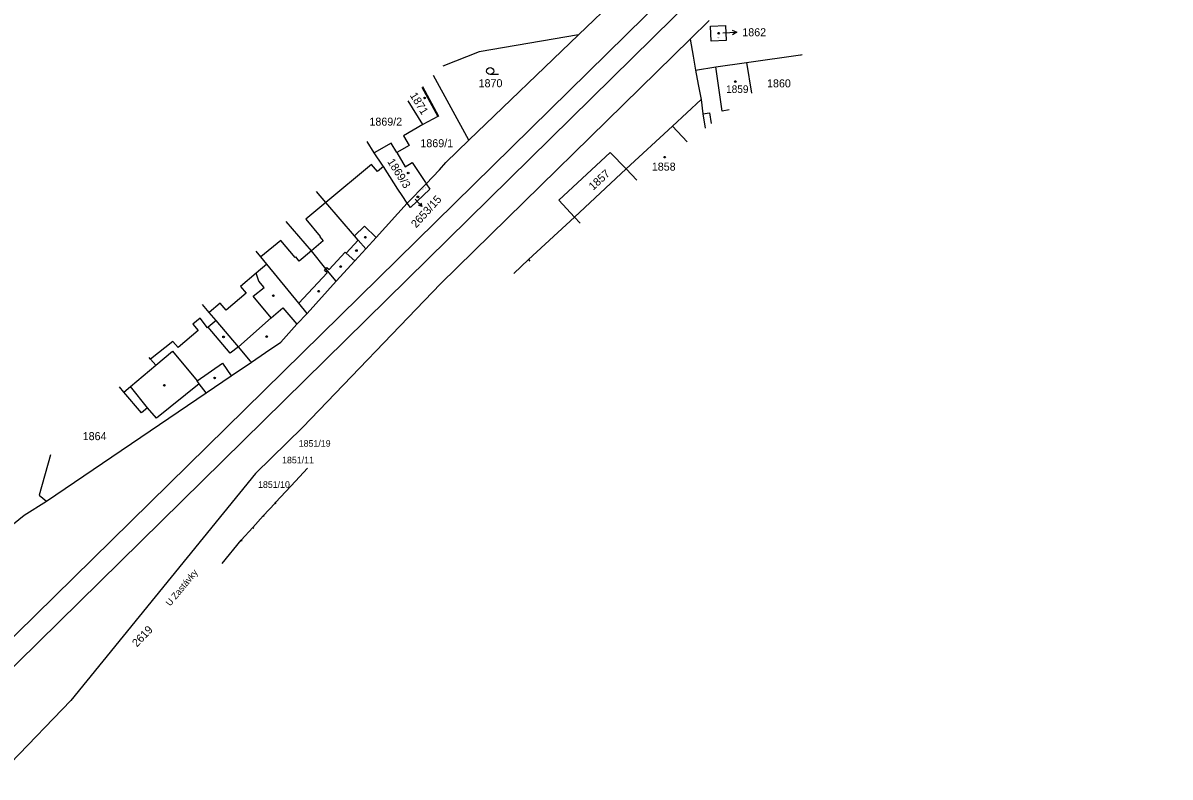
# Model space of a CAD drawing. Extents: x -825057 to -819383, y -1071633 to -1067888.
# Drawn here: x -819637.1 to -819393.5, y -1069088.6 to -1068928.5 of the extents above; entities that cross this region are included whole.
import ezdxf

# ---------------------------------------------------------------- set-up
doc = ezdxf.new("R2010")
doc.units = 0
for name, color, linetype in [('Vrstva 1', 7, 'Continuous'), ('Vrstva 10', 7, 'Continuous'), ('Vrstva 15', 7, 'Continuous'), ('Vrstva 16', 7, 'Continuous'), ('Vrstva 18', 7, 'Continuous'), ('Vrstva 19', 7, 'Continuous'), ('Vrstva 25', 7, 'Continuous'), ('Vrstva 4', 7, 'Continuous')]:
    doc.layers.add(name, color=color, linetype=linetype)

msp = doc.modelspace()

# ---------------------------------------------------------------- linework, layer by layer
at = {"layer": 'Vrstva 1'}
for p, q in [((-819519.1, -1068931.03), (-819503.43, -1068916.02)), ((-819491.32, -1068927.98), (-819495.4, -1068931.98)), ((-819542.35, -1068953.43), (-819519.1, -1068931.03)), ((-819519.1, -1068931.03), (-819540.17, -1068934.68)), ((-819491.07, -1068929.21), (-819487.91, -1068929.05)), ((-819490.92, -1068932.37), (-819491.07, -1068929.21)), ((-819487.91, -1068929.05), (-819487.75, -1068932.21)), ((-819495.4, -1068931.98), (-819548.4, -1068983.89)), ((-819495.4, -1068931.98), (-819494.75, -1068935.57)), ((-819487.75, -1068932.21), (-819490.92, -1068932.37)), ((-819540.17, -1068934.68), (-819547.89, -1068937.7)), ((-819494.75, -1068935.57), (-819494.22, -1068938.52)), ((-819483.41, -1068936.92), (-819471.97, -1068935.25)), ((-819471.97, -1068935.25), (-819471.6, -1068935.2)), ((-819471.97, -1068935.25), (-819471.94, -1068935.45)), ((-819494.22, -1068938.52), (-819489.95, -1068937.86)), ((-819494.22, -1068938.52), (-819493.67, -1068941.57)), ((-819489.95, -1068937.86), (-819483.41, -1068936.92)), ((-819483.41, -1068936.92), (-819482.39, -1068943.39)), ((-819542.35, -1068953.43), (-819549.86, -1068939.66)), ((-819552.25, -1068942.02), (-819548.82, -1068948.31)), ((-819493.67, -1068941.57), (-819493.08, -1068944.79)), ((-819552.14, -1068950.11), (-819555.27, -1068945.02)), ((-819493.08, -1068944.79), (-819499.16, -1068950.4)), ((-819493.08, -1068944.79), (-819492.69, -1068947.79)), ((-819548.82, -1068948.31), (-819548.99, -1068948.4)), ((-819492.69, -1068947.79), (-819492.18, -1068950.82)), ((-819552.14, -1068950.11), (-819556.24, -1068952.51)), ((-819548.99, -1068948.4), (-819552.14, -1068950.11)), ((-819499.16, -1068950.4), (-819508.94, -1068959.47)), ((-819556.24, -1068952.51), (-819555.06, -1068954.54)), ((-819562.45, -1068956.06), (-819564, -1068953.67)), ((-819558.89, -1068954.02), (-819562.45, -1068956.06)), ((-819557.68, -1068956.03), (-819558.89, -1068954.02)), ((-819555.06, -1068954.54), (-819557.68, -1068956.03)), ((-819547.27, -1068958.17), (-819542.35, -1068953.43)), ((-819560.72, -1068958.72), (-819562.45, -1068956.06)), ((-819557.68, -1068956.03), (-819555.87, -1068959.03)), ((-819512.39, -1068955.99), (-819523.26, -1068966.11)), ((-819508.94, -1068959.47), (-819512.39, -1068955.99)), ((-819560.53, -1068959.01), (-819560.72, -1068958.72)), ((-819558.31, -1068962.43), (-819560.53, -1068959.01)), ((-819555.87, -1068959.03), (-819554.4, -1068958.16)), ((-819554.4, -1068958.16), (-819551.61, -1068962.38)), ((-819551.44, -1068962.65), (-819548.59, -1068959.7)), ((-819548.59, -1068959.7), (-819547.27, -1068958.17)), ((-819508.94, -1068959.47), (-819519.95, -1068969.72)), ((-819508.94, -1068959.47), (-819506.72, -1068961.87)), ((-819557.43, -1068963.78), (-819558.31, -1068962.43)), ((-819555.46, -1068966.81), (-819551.44, -1068962.65)), ((-819551.61, -1068962.38), (-819551.44, -1068962.65)), ((-819551.44, -1068962.65), (-819550.66, -1068963.82)), ((-819572.74, -1068966.66), (-819574.73, -1068964.3)), ((-819556.56, -1068965.13), (-819557.43, -1068963.78)), ((-819555.46, -1068966.81), (-819556.56, -1068965.13)), ((-819550.66, -1068963.82), (-819554.74, -1068967.73)), ((-819566.69, -1068973.69), (-819572.74, -1068966.66)), ((-819562.05, -1068974.06), (-819555.46, -1068966.81)), ((-819554.74, -1068967.73), (-819555.46, -1068966.81)), ((-819523.26, -1068966.11), (-819519.95, -1068969.72)), ((-819519.95, -1068969.72), (-819529.74, -1068978.75)), ((-819519.95, -1068969.72), (-819518.74, -1068971)), ((-819575.82, -1068976.91), (-819581.14, -1068970.66)), ((-819565.88, -1068974.64), (-819566.69, -1068973.69)), ((-819564.27, -1068976.5), (-819565.88, -1068974.64)), ((-819564.27, -1068976.5), (-819562.05, -1068974.06)), ((-819586.52, -1068978.19), (-819587.54, -1068977)), ((-819572.73, -1068980.69), (-819575.82, -1068976.91)), ((-819566.58, -1068979.02), (-819564.27, -1068976.5)), ((-819585.24, -1068979.75), (-819586.52, -1068978.19)), ((-819578.49, -1068988.04), (-819585.24, -1068979.75)), ((-819570.53, -1068983.33), (-819566.58, -1068979.02)), ((-819529.74, -1068978.75), (-819532.85, -1068981.71)), ((-819529.74, -1068978.75), (-819529.42, -1068979.1)), ((-819570.53, -1068983.33), (-819572.73, -1068980.69)), ((-819548.4, -1068983.89), (-819577.66, -1069014.36)), ((-819576.73, -1068990.2), (-819570.53, -1068983.33)), ((-819597.52, -1068989.97), (-819598.94, -1068988.29)), ((-819576.73, -1068990.2), (-819578.49, -1068988.04)), ((-819596.03, -1068991.72), (-819597.52, -1068989.97)), ((-819591.26, -1068997.31), (-819596.03, -1068991.72)), ((-819578.88, -1068992.48), (-819576.73, -1068990.2)), ((-819582.32, -1068996.26), (-819578.88, -1068992.48)), ((-819585.57, -1068998.49), (-819582.32, -1068996.26)), ((-819588.71, -1069000.3), (-819591.26, -1068997.31)), ((-819588.52, -1069000.53), (-819585.57, -1068998.49)), ((-819592.84, -1069003.45), (-819588.52, -1069000.53)), ((-819588.52, -1069000.53), (-819588.71, -1069000.3)), ((-819598.18, -1069007.07), (-819592.84, -1069003.45)), ((-819615.6, -1069006.9), (-819616.56, -1069005.75)), ((-819599.61, -1069005.14), (-819608.7, -1069012.44)), ((-819598.18, -1069007.07), (-819599.61, -1069005.14)), ((-819632.07, -1069030.01), (-819598.18, -1069007.07)), ((-819611.9, -1069011.32), (-819615.6, -1069006.9)), ((-819610.61, -1069010.22), (-819611.9, -1069011.32)), ((-819608.7, -1069012.44), (-819610.61, -1069010.22)), ((-819577.66, -1069014.36), (-819587.71, -1069024.18)), ((-819631.17, -1069020.23), (-819633.59, -1069028.78)), ((-819579.17, -1069025.81), (-819576.62, -1069023.05)), ((-819587.71, -1069024.18), (-819626.91, -1069072.36)), ((-819583.33, -1069030.24), (-819579.17, -1069025.81)), ((-819636.82, -1069032.99), (-819632.07, -1069030.01)), ((-819633.59, -1069028.78), (-819632.07, -1069030.01)), ((-819586.02, -1069033.17), (-819583.53, -1069030.45)), ((-819583.53, -1069030.45), (-819583.33, -1069030.24)), ((-819583.19, -1069030.36), (-819583.33, -1069030.24)), ((-819659.02, -1069051.19), (-819636.82, -1069032.99)), ((-819588.24, -1069035.6), (-819586.02, -1069033.17)), ((-819585.84, -1069033.31), (-819586.02, -1069033.17)), ((-819590.73, -1069038.32), (-819588.24, -1069035.6)), ((-819588.24, -1069035.6), (-819588.04, -1069035.76)), ((-819594.78, -1069043.27), (-819590.73, -1069038.32)), ((-819590.73, -1069038.32), (-819590.5, -1069038.51)), ((-819626.91, -1069072.36), (-819639.73, -1069085.69))]:
    msp.add_line(p, q, dxfattribs=at)
at = {"layer": 'Vrstva 10'}
for p, q in [((-819896.02, -1069311.23), (-819396.47, -1068820.5)), ((-819393.49, -1068823.65), (-819892.75, -1069314.72))]:
    msp.add_line(p, q, dxfattribs=at)
at = {"layer": 'Vrstva 16'}
for p, q in [((-819488.45, -1068930.64), (-819485.454, -1068930.488)), ((-819553.78, -1068965.94), (-819552.327, -1068967.456))]:
    msp.add_line(p, q, dxfattribs=at)
for points in [[(-819486.478, -1068930.039), (-819485.454, -1068930.488), (-819486.427, -1068931.038)], [(-819552.559, -1068966.709), (-819552.327, -1068967.456), (-819553.064, -1068967.193)]]:
    msp.add_lwpolyline(points, dxfattribs=at)
at = {"layer": 'Vrstva 25'}
msp.add_line((-819536.1, -1068939.48), (-819537.85, -1068939.48), dxfattribs=at)
for centre, radius in [((-819489.33, -1068930.7), 0.175), ((-819537.85, -1068938.73), 0.75), ((-819485.8, -1068940.96), 0.175), ((-819551.77, -1068944.44), 0.175), ((-819500.79, -1068957.01), 0.175), ((-819555.26, -1068960.36), 0.175), ((-819553.2, -1068965.44), 0.175), ((-819564.34, -1068974), 0.175), ((-819566.24, -1068976.83), 0.175), ((-819569.58, -1068980.24), 0.175), ((-819583.88, -1068986.42), 0.175), ((-819574.25, -1068985.47), 0.175), ((-819594.46, -1068995.16), 0.175), ((-819585.29, -1068995.09), 0.175), ((-819596.35, -1069003.88), 0.175), ((-819607.02, -1069005.44), 0.175)]:
    msp.add_circle(centre, radius, dxfattribs=at)
at = {"layer": 'Vrstva 4'}
for p, q in [((-819488.59, -1068947.21), (-819489.95, -1068937.86)), ((-819552.38, -1068942.16), (-819548.99, -1068948.4)), ((-819492.69, -1068947.79), (-819491.28, -1068947.59)), ((-819491.28, -1068947.59), (-819490.95, -1068949.89)), ((-819487.12, -1068946.98), (-819488.59, -1068947.21)), ((-819499.16, -1068950.4), (-819496.04, -1068953.75)), ((-819563.03, -1068958.54), (-819572.74, -1068966.66)), ((-819561.76, -1068960.07), (-819563.03, -1068958.54)), ((-819560.53, -1068959.01), (-819561.76, -1068960.07)), ((-819572.74, -1068966.66), (-819576.96, -1068970.2)), ((-819576.96, -1068970.2), (-819573.93, -1068973.82)), ((-819566.69, -1068973.69), (-819564.5, -1068971.64)), ((-819564.5, -1068971.64), (-819562.05, -1068974.06)), ((-819582.29, -1068974.67), (-819586.52, -1068978.19)), ((-819579.26, -1068978.31), (-819582.29, -1068974.67)), ((-819573.32, -1068974.75), (-819575.82, -1068976.91)), ((-819573.93, -1068973.82), (-819574.04, -1068973.92)), ((-819574.04, -1068973.92), (-819573.32, -1068974.75)), ((-819568.4, -1068977.36), (-819565.88, -1068974.64)), ((-819575.82, -1068976.91), (-819578.4, -1068979.08)), ((-819572.06, -1068980.89), (-819568.63, -1068977.15)), ((-819568.63, -1068977.15), (-819568.4, -1068977.36)), ((-819568.4, -1068977.36), (-819566.58, -1068979.02)), ((-819585.24, -1068979.75), (-819587.54, -1068981.67)), ((-819579.13, -1068978.2), (-819579.26, -1068978.31)), ((-819578.4, -1068979.08), (-819579.13, -1068978.2)), ((-819587.54, -1068981.67), (-819590.87, -1068984.45)), ((-819586.98, -1068983.33), (-819587.54, -1068981.67)), ((-819578.49, -1068988.04), (-819572.49, -1068981.58)), ((-819573.06, -1068981.05), (-819572.73, -1068980.69)), ((-819572.49, -1068981.58), (-819573.06, -1068981.05)), ((-819572.73, -1068980.69), (-819572.52, -1068980.47)), ((-819572.52, -1068980.47), (-819572.06, -1068980.89)), ((-819590.87, -1068984.45), (-819589.65, -1068985.88)), ((-819588.15, -1068986.55), (-819585.84, -1068984.68)), ((-819585.84, -1068984.68), (-819586.98, -1068983.33)), ((-819589.65, -1068985.88), (-819593.92, -1068989.51)), ((-819584.35, -1068991.15), (-819588.15, -1068986.55)), ((-819595.19, -1068988.03), (-819597.52, -1068989.97)), ((-819593.92, -1068989.51), (-819595.19, -1068988.03)), ((-819584.35, -1068991.15), (-819581.9, -1068989.03)), ((-819581.9, -1068989.03), (-819578.88, -1068992.48)), ((-819599.43, -1068991.16), (-819601, -1068992.49)), ((-819597.85, -1068993.21), (-819599.43, -1068991.16)), ((-819596.03, -1068991.72), (-819597.74, -1068993.12)), ((-819591.26, -1068997.31), (-819584.35, -1068991.15)), ((-819599.87, -1068993.81), (-819604.13, -1068997.43)), ((-819601, -1068992.49), (-819599.87, -1068993.81)), ((-819597.74, -1068993.12), (-819597.85, -1068993.21)), ((-819593.03, -1068998.61), (-819597.74, -1068993.12)), ((-819605.25, -1068996.12), (-819609.95, -1068999.89)), ((-819604.13, -1068997.43), (-819605.25, -1068996.12)), ((-819608.84, -1069001.18), (-819605.28, -1068998.18)), ((-819605.28, -1068998.18), (-819600.07, -1069004.53)), ((-819591.26, -1068997.31), (-819593.03, -1068998.61)), ((-819614.23, -1069005.73), (-819608.84, -1069001.18)), ((-819609.95, -1068999.89), (-819610.27, -1068999.52)), ((-819609.95, -1068999.89), (-819608.84, -1069001.18)), ((-819600.07, -1069004.53), (-819594.67, -1069000.76)), ((-819594.67, -1069000.76), (-819592.84, -1069003.45)), ((-819615.6, -1069006.9), (-819614.23, -1069005.73)), ((-819610.61, -1069010.22), (-819614.23, -1069005.73)), ((-819599.61, -1069005.14), (-819600.07, -1069004.53)), ((-819579.14, -1069025.84), (-819579.17, -1069025.81)), ((-819583.53, -1069030.45), (-819583.38, -1069030.57))]:
    msp.add_line(p, q, dxfattribs=at)

# ---------------------------------------------------------------- texts
at = {"layer": 'Vrstva 15'}
msp.add_text('U Zastávky', height=1.4, rotation=50.4, dxfattribs=at).set_placement((-819605.798, -1069052.445))
at = {"layer": 'Vrstva 16'}
for s, height, p in [('1862', 1.7, (-819484.314, -1068931.34)), ('1851/19', 1.4, (-819578.492, -1069018.49)), ('1851/11', 1.4, (-819582.032, -1069022.01)), ('1851/10', 1.4, (-819587.138, -1069027.22))]:
    msp.add_text(s, height=height, dxfattribs=at).set_placement(p)
msp.add_text('2653/15', height=1.7, rotation=47.7, dxfattribs=at).set_placement((-819553.572, -1068972.159))
at = {"layer": 'Vrstva 18'}
for s, p in [('1870', (-819540.307, -1068942.16)), ('1864', (-819624.369, -1069017.09))]:
    msp.add_text(s, height=1.7, dxfattribs=at).set_placement(p)
for s, rotation, p in [('1857', 42.3, (-819515.989, -1068964.152)), ('2619', 45.9, (-819612.854, -1069061.111))]:
    msp.add_text(s, height=1.7, rotation=rotation, dxfattribs=at).set_placement(p)
at = {"layer": 'Vrstva 19'}
for s, height, p in [('1862', 0.2, (-819489.777, -1068931.8)), ('1860', 1.7, (-819479.062, -1068942.19)), ('1859', 1.6, (-819487.76, -1068943.37)), ('1869/2', 1.7, (-819563.489, -1068950.32)), ('1869/1', 1.7, (-819552.666, -1068954.9)), ('1858', 1.7, (-819503.528, -1068959.87))]:
    msp.add_text(s, height=height, dxfattribs=at).set_placement(p)
for s, height, rotation, p in [('1871', 1.7, 301.5, (-819554.971, -1068943.875)), ('1869/3', 1.7, 302.4, (-819559.768, -1068957.954)), ('2653/15', 0.2, 43.2, (-819552.163, -1068964.146))]:
    msp.add_text(s, height=height, rotation=rotation, dxfattribs=at).set_placement(p)

doc.saveas('drawing.dxf')
